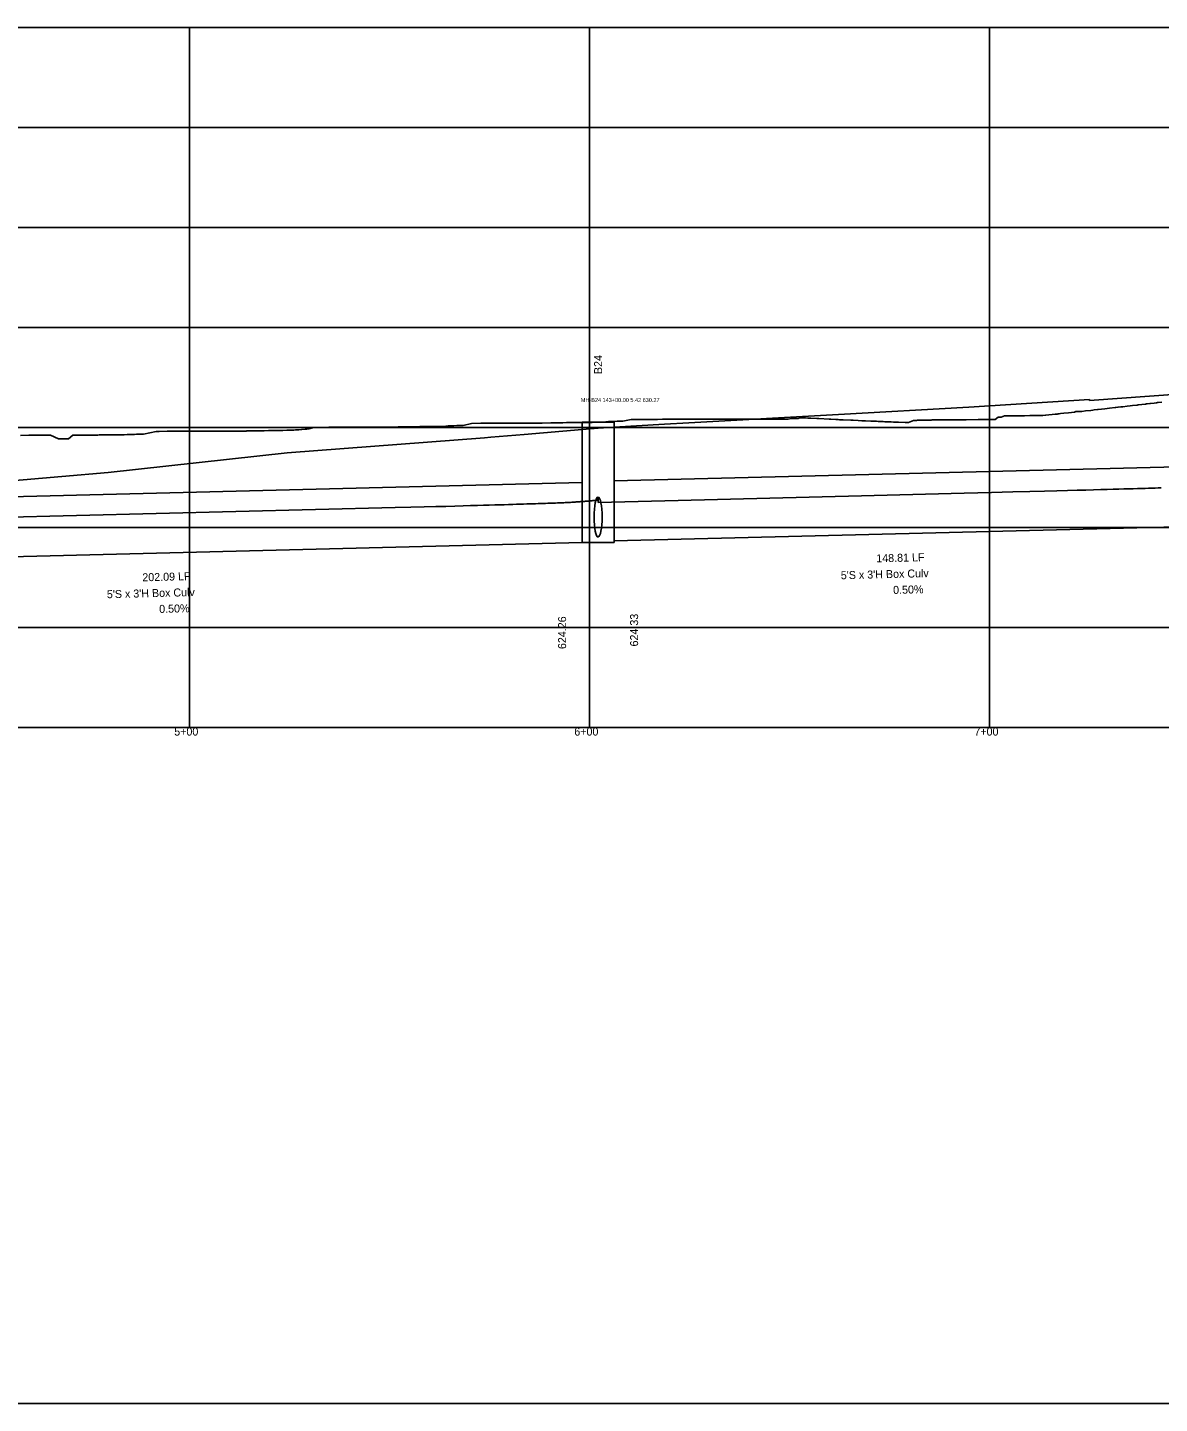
# Model space of a CAD drawing. Extents: x 2253035 to 2279930, y 13774972 to 13793443.
# Drawn here: x 2260421 to 2260703.9, y 13791972.5 to 13792316.4 of the extents above; entities that cross this region are included whole.
import ezdxf

# ---------------------------------------------------------------- set-up
doc = ezdxf.new("R2010")
doc.units = 0
for name, color, linetype in [('Default', 7, 'Continuous'), ('E_Utility_ATT_HH', 7, 'Continuous'), ('E_Utility_ATT_PR_PVC', 7, 'Continuous'), ('E_Utility_Telephone_Telephone Pedestal_TPED_Description', 7, 'Continuous'), ('E_Utillity_Water_Water Line_12in', 7, 'Continuous'), ('E_Utillity_Water_Water Line_1in', 7, 'Continuous'), ('E_Utillity_Water_Water Line_4in', 7, 'Continuous'), ('E_Utillity_Water_Water Line_8in', 7, 'Continuous')]:
    doc.layers.add(name, color=color, linetype=linetype)

msp = doc.modelspace()

# ---------------------------------------------------------------- linework, layer by layer
at = {"layer": 'Default'}
for p, q in [((2260461.48, 13792141.44), (2260461.48, 13792316.44)), ((2260561.48, 13792141.44), (2260561.48, 13792316.44)), ((2260661.48, 13792141.44), (2260661.48, 13792316.44)), ((2259961.48, 13792291.44), (2261350.66, 13792291.44)), ((2259961.48, 13792266.44), (2261350.66, 13792266.44)), ((2259961.48, 13792241.44), (2261350.66, 13792241.44)), ((2259961.48, 13792216.44), (2261350.66, 13792216.44)), ((2259961.48, 13792191.44), (2261350.66, 13792191.44)), ((2259961.48, 13792166.44), (2261350.66, 13792166.44)), ((2258357.4, 13791972.48), (2265626.63, 13791972.48))]:
    msp.add_line(p, q, dxfattribs=at)
msp.add_lwpolyline([(2259961.48, 13792141.44), (2259961.48, 13792316.44), (2261350.66, 13792316.44), (2261350.66, 13792141.44)], close=True, dxfattribs=at)
at = {"layer": 'E_Utility_ATT_PR_PVC'}
msp.add_line((2260563.63, 13792198.87), (2260563.63, 13792197.73), dxfattribs=at)
for points in [[(2260353.54, 13792192.44), (2260512.87, 13792196.42), (2260516.81, 13792196.52), (2260520.15, 13792196.61), (2260523.05, 13792196.69), (2260525.59, 13792196.75), (2260527.86, 13792196.82), (2260529.91, 13792196.87), (2260531.76, 13792196.92), (2260533.45, 13792196.97), (2260535.01, 13792197.02), (2260536.44, 13792197.06), (2260537.78, 13792197.09), (2260539.02, 13792197.13), (2260540.17, 13792197.16), (2260541.26, 13792197.2), (2260542.28, 13792197.23), (2260543.24, 13792197.26), (2260544.14, 13792197.28), (2260545, 13792197.31), (2260545.81, 13792197.34), (2260546.58, 13792197.36), (2260547.31, 13792197.38), (2260548.01, 13792197.41), (2260548.67, 13792197.43), (2260549.3, 13792197.45), (2260549.9, 13792197.47), (2260550.48, 13792197.49), (2260551.03, 13792197.51), (2260551.55, 13792197.52), (2260552.06, 13792197.54), (2260552.54, 13792197.56), (2260553, 13792197.57), (2260553.45, 13792197.59), (2260553.88, 13792197.61), (2260554.29, 13792197.62), (2260554.68, 13792197.64), (2260555.06, 13792197.65), (2260555.42, 13792197.67), (2260555.77, 13792197.68), (2260556.11, 13792197.7), (2260556.44, 13792197.73), (2260556.75, 13792197.75), (2260557.05, 13792197.77), (2260557.34, 13792197.79), (2260557.62, 13792197.81), (2260557.89, 13792197.82), (2260558.15, 13792197.84), (2260558.4, 13792197.86), (2260558.64, 13792197.88), (2260558.87, 13792197.89), (2260559.09, 13792197.91), (2260559.31, 13792197.92), (2260559.52, 13792197.94), (2260559.72, 13792197.96), (2260559.91, 13792197.97), (2260560.09, 13792197.98), (2260560.27, 13792198), (2260560.45, 13792198.01), (2260560.61, 13792198.02), (2260560.77, 13792198.04), (2260560.93, 13792198.05), (2260561.07, 13792198.06), (2260561.22, 13792198.08), (2260561.35, 13792198.09), (2260561.48, 13792198.1), (2260561.61, 13792198.11), (2260561.73, 13792198.12), (2260561.85, 13792198.13), (2260561.96, 13792198.14), (2260562.07, 13792198.15), (2260562.17, 13792198.16), (2260562.27, 13792198.17), (2260562.36, 13792198.18), (2260562.45, 13792198.19), (2260562.54, 13792198.2), (2260562.62, 13792198.21), (2260562.7, 13792198.22), (2260562.77, 13792198.23), (2260562.84, 13792198.24), (2260562.91, 13792198.24), (2260562.97, 13792198.25), (2260563.03, 13792198.26), (2260563.09, 13792198.27), (2260563.14, 13792198.28), (2260563.19, 13792198.28), (2260563.24, 13792198.29), (2260563.28, 13792198.3), (2260563.33, 13792198.31), (2260563.36, 13792198.31), (2260563.4, 13792198.32), (2260563.43, 13792198.33), (2260563.46, 13792198.33), (2260563.49, 13792198.34), (2260563.51, 13792198.34), (2260563.54, 13792198.35), (2260563.55, 13792198.36), (2260563.57, 13792198.36), (2260563.59, 13792198.37), (2260563.6, 13792198.37), (2260563.61, 13792198.38), (2260563.62, 13792198.39), (2260563.62, 13792198.39), (2260563.62, 13792198.4), (2260563.63, 13792198.4), (2260563.63, 13792198.87)], [(2260563.63, 13792197.73), (2260583.67, 13792198.23), (2260629.46, 13792199.38), (2260645.48, 13792199.78), (2260655.12, 13792200.03), (2260661.98, 13792200.2), (2260667.27, 13792200.34), (2260671.57, 13792200.45), (2260675.18, 13792200.55), (2260678.28, 13792200.63), (2260680.99, 13792200.7), (2260683.39, 13792200.77), (2260685.54, 13792200.83), (2260687.49, 13792200.88), (2260689.26, 13792200.93), (2260690.88, 13792200.98), (2260692.38, 13792201.02), (2260693.76, 13792201.06), (2260695.05, 13792201.1), (2260696.25, 13792201.13), (2260697.38, 13792201.16), (2260698.43, 13792201.2), (2260699.42, 13792201.23), (2260700.36, 13792201.25), (2260701.24, 13792201.28), (2260702.08, 13792201.31), (2260702.87, 13792201.33), (2260703.62, 13792201.36), (2260704.34, 13792201.38)]]:
    msp.add_lwpolyline(points, dxfattribs=at)
at = {"layer": 'E_Utillity_Water_Water Line_12in'}
msp.add_lwpolyline([(2260559.63, 13792217.78), (2260567.63, 13792217.78), (2260567.63, 13792187.74), (2260559.63, 13792187.74)], close=True, dxfattribs=at)
at = {"layer": 'E_Utillity_Water_Water Line_1in'}
msp.add_lwpolyline([(2260385.04, 13792200.38), (2260429.58, 13792204.18), (2260441.19, 13792205.21), (2260485.92, 13792210.11), (2260535.24, 13792213.87), (2260536.85, 13792214.02), (2260545.19, 13792214.71), (2260559.63, 13792215.93), (2260559.63, 13792215.93), (2260563.63, 13792216.25), (2260563.63, 13792216.25), (2260567.63, 13792216.57), (2260567.63, 13792216.57), (2260580.25, 13792217.3), (2260586.29, 13792217.65), (2260623.69, 13792219.68), (2260656.31, 13792221.55), (2260686.45, 13792223.42), (2260686.48, 13792223.21), (2260716.44, 13792225.36)], dxfattribs=at)
at = {"layer": 'E_Utillity_Water_Water Line_4in'}
for p, q in [((2260567.63, 13792203.1), (2260716.44, 13792206.82)), ((2260357.54, 13792197.69), (2260559.63, 13792202.74)), ((2260567.63, 13792188.1), (2260716.44, 13792191.82)), ((2260357.54, 13792182.69), (2260559.63, 13792187.74))]:
    msp.add_line(p, q, dxfattribs=at)
msp.add_ellipse((2260563.63, 13792194.07), major_axis=(0, 5), ratio=0.2, dxfattribs=at)
at = {"layer": 'E_Utillity_Water_Water Line_8in'}
msp.add_lwpolyline([(2260419.22, 13792214.49), (2260421.3, 13792214.5), (2260421.35, 13792214.5), (2260423.52, 13792214.5), (2260424.01, 13792214.5), (2260424.56, 13792214.5), (2260426.79, 13792214.51), (2260428.78, 13792213.65), (2260431.26, 13792213.66), (2260432.38, 13792214.52), (2260432.64, 13792214.53), (2260433.62, 13792214.53), (2260433.99, 13792214.55), (2260435.27, 13792214.55), (2260437.23, 13792214.55), (2260437.41, 13792214.56), (2260438.62, 13792214.57), (2260438.92, 13792214.59), (2260439.85, 13792214.59), (2260441.77, 13792214.59), (2260442.26, 13792214.63), (2260443.62, 13792214.63), (2260445.14, 13792214.64), (2260445.93, 13792214.72), (2260447.74, 13792214.73), (2260448.23, 13792214.79), (2260448.35, 13792214.79), (2260448.62, 13792214.79), (2260450.04, 13792214.8), (2260453.16, 13792215.44), (2260453.41, 13792215.45), (2260453.95, 13792215.46), (2260455.93, 13792215.51), (2260459.29, 13792215.52), (2260459.5, 13792215.52), (2260461.49, 13792215.52), (2260461.53, 13792215.52), (2260461.58, 13792215.52), (2260463.7, 13792215.53), (2260464.17, 13792215.53), (2260466.07, 13792215.53), (2260468.03, 13792215.53), (2260468.76, 13792215.53), (2260470.2, 13792215.54), (2260472.3, 13792215.54), (2260472.65, 13792215.56), (2260473.62, 13792215.56), (2260473.65, 13792215.56), (2260473.86, 13792215.57), (2260475.14, 13792215.57), (2260475.56, 13792215.57), (2260475.67, 13792215.58), (2260475.86, 13792215.59), (2260477.73, 13792215.59), (2260478.47, 13792215.59), (2260478.97, 13792215.59), (2260480.14, 13792215.6), (2260481.25, 13792215.67), (2260482.02, 13792215.68), (2260483.57, 13792215.68), (2260483.62, 13792215.68), (2260483.97, 13792215.71), (2260484.55, 13792215.72), (2260484.83, 13792215.74), (2260485.8, 13792215.75), (2260486.57, 13792215.83), (2260487.61, 13792215.83), (2260487.98, 13792215.88), (2260488.62, 13792215.88), (2260488.86, 13792215.91), (2260489.51, 13792215.92), (2260490.46, 13792216.08), (2260490.8, 13792216.08), (2260491.34, 13792216.09), (2260492.57, 13792216.44), (2260494.12, 13792216.48), (2260494.39, 13792216.49), (2260496.31, 13792216.54), (2260499.58, 13792216.54), (2260499.79, 13792216.54), (2260502.46, 13792216.55), (2260502.51, 13792216.55), (2260503.87, 13792216.55), (2260504.33, 13792216.55), (2260504.85, 13792216.55), (2260507.33, 13792216.56), (2260508.8, 13792216.56), (2260510.2, 13792216.56), (2260512.25, 13792216.56), (2260512.68, 13792216.58), (2260513.62, 13792216.59), (2260514.23, 13792216.61), (2260515.41, 13792216.62), (2260517.23, 13792216.62), (2260517.51, 13792216.64), (2260518.62, 13792216.64), (2260519.1, 13792216.67), (2260519.94, 13792216.67), (2260521.67, 13792216.67), (2260522.43, 13792216.73), (2260523.62, 13792216.74), (2260524.95, 13792216.74), (2260526.15, 13792216.86), (2260527.61, 13792216.87), (2260528.33, 13792216.96), (2260528.42, 13792216.96), (2260528.62, 13792216.96), (2260528.8, 13792216.97), (2260529.92, 13792216.97), (2260531.97, 13792217.44), (2260534.31, 13792217.5), (2260534.82, 13792217.52), (2260536.69, 13792217.56), (2260539.88, 13792217.57), (2260540.07, 13792217.57), (2260541.96, 13792217.57), (2260541.99, 13792217.57), (2260542.04, 13792217.57), (2260544.04, 13792217.58), (2260544.49, 13792217.58), (2260546.29, 13792217.58), (2260548.15, 13792217.58), (2260548.84, 13792217.58), (2260549.62, 13792217.58), (2260551.81, 13792217.59), (2260552.34, 13792217.61), (2260552.46, 13792217.61), (2260553.62, 13792217.61), (2260553.78, 13792217.62), (2260554.79, 13792217.62), (2260555.7, 13792217.67), (2260557.8, 13792217.67), (2260558.62, 13792217.67), (2260559.19, 13792217.71), (2260559.63, 13792217.71), (2260559.63, 13792217.71), (2260560.34, 13792217.71), (2260562.16, 13792217.71), (2260563, 13792217.78), (2260563.13, 13792217.78), (2260563.62, 13792217.78), (2260563.63, 13792217.78), (2260563.63, 13792217.78), (2260564.87, 13792217.78), (2260566.24, 13792217.92), (2260567.55, 13792217.92), (2260567.63, 13792217.93), (2260567.63, 13792217.93), (2260568.37, 13792218.02), (2260568.44, 13792218.02), (2260568.62, 13792218.02), (2260568.78, 13792218.02), (2260569.81, 13792218.01), (2260571.91, 13792218.44), (2260573.23, 13792218.44), (2260573.39, 13792218.44), (2260573.71, 13792218.44), (2260574.94, 13792218.44), (2260576.18, 13792218.44), (2260578.51, 13792218.44), (2260579.74, 13792218.54), (2260581.62, 13792218.54), (2260581.67, 13792218.54), (2260581.67, 13792218.54), (2260583.74, 13792218.53), (2260584.19, 13792218.53), (2260584.71, 13792218.53), (2260587.22, 13792218.52), (2260588.75, 13792218.52), (2260589.58, 13792218.52), (2260591.95, 13792218.51), (2260592.21, 13792218.52), (2260592.34, 13792218.52), (2260593.63, 13792218.52), (2260593.69, 13792218.52), (2260594.87, 13792218.52), (2260597.06, 13792218.51), (2260597.36, 13792218.53), (2260598.63, 13792218.52), (2260598.82, 13792218.53), (2260600.24, 13792218.53), (2260602.54, 13792218.52), (2260602.78, 13792218.54), (2260602.95, 13792218.54), (2260603.63, 13792218.53), (2260603.83, 13792218.55), (2260604.56, 13792218.54), (2260606.56, 13792218.53), (2260606.91, 13792218.57), (2260608.63, 13792218.55), (2260608.96, 13792218.55), (2260611.12, 13792218.53), (2260611.91, 13792218.71), (2260613.51, 13792218.67), (2260613.57, 13792218.67), (2260613.63, 13792218.7), (2260614.03, 13792218.91), (2260614.28, 13792218.9), (2260614.73, 13792218.88), (2260615.43, 13792218.84), (2260616.05, 13792218.81), (2260616.8, 13792218.77), (2260618.29, 13792218.69), (2260618.57, 13792218.68), (2260618.63, 13792218.68), (2260618.71, 13792218.67), (2260618.83, 13792218.67), (2260621.37, 13792218.54), (2260621.65, 13792218.53), (2260621.79, 13792218.52), (2260623.04, 13792218.46), (2260623.38, 13792218.44), (2260623.62, 13792218.43), (2260623.63, 13792218.43), (2260624, 13792218.41), (2260624.05, 13792218.41), (2260624.91, 13792218.37), (2260626.8, 13792218.28), (2260627.05, 13792218.27), (2260627.09, 13792218.27), (2260627.36, 13792218.26), (2260628.63, 13792218.2), (2260629.57, 13792218.16), (2260629.93, 13792218.14), (2260629.94, 13792218.14), (2260630.49, 13792218.12), (2260631.8, 13792218.06), (2260632.63, 13792218.02), (2260633.24, 13792218), (2260633.63, 13792217.98), (2260634.08, 13792217.96), (2260634.88, 13792217.93), (2260635.27, 13792217.91), (2260636.9, 13792217.85), (2260637.49, 13792217.82), (2260638.02, 13792217.8), (2260638.45, 13792217.78), (2260638.64, 13792217.77), (2260638.75, 13792217.77), (2260640.34, 13792217.71), (2260640.82, 13792217.69), (2260641.22, 13792217.67), (2260642.49, 13792218.21), (2260642.51, 13792218.21), (2260642.53, 13792218.22), (2260642.54, 13792218.22), (2260643.23, 13792218.21), (2260643.46, 13792218.29), (2260643.64, 13792218.29), (2260643.65, 13792218.29), (2260644.31, 13792218.29), (2260644.95, 13792218.28), (2260645.21, 13792218.33), (2260645.34, 13792218.33), (2260645.34, 13792218.33), (2260645.34, 13792218.33), (2260645.67, 13792218.33), (2260645.67, 13792218.33), (2260645.67, 13792218.33), (2260646.87, 13792218.32), (2260647.16, 13792218.37), (2260647.42, 13792218.37), (2260648.6, 13792218.36), (2260648.64, 13792218.37), (2260649.75, 13792218.37), (2260649.8, 13792218.37), (2260652.15, 13792218.37), (2260652.39, 13792218.39), (2260652.59, 13792218.38), (2260652.77, 13792218.38), (2260652.89, 13792218.39), (2260653.01, 13792218.39), (2260653.04, 13792218.39), (2260653.07, 13792218.39), (2260653.31, 13792218.39), (2260653.56, 13792218.39), (2260655.4, 13792218.4), (2260655.62, 13792218.41), (2260658.62, 13792218.42), (2260659.1, 13792218.42), (2260661.09, 13792218.43), (2260661.11, 13792218.43), (2260661.3, 13792218.43), (2260661.32, 13792218.43), (2260662.72, 13792218.44), (2260662.85, 13792218.44), (2260663.62, 13792219.01), (2260663.7, 13792219.01), (2260663.72, 13792219.03), (2260664.4, 13792219.05), (2260665.17, 13792219.36), (2260666.29, 13792219.37), (2260667.82, 13792219.38), (2260668.61, 13792219.39), (2260668.64, 13792219.39), (2260670.21, 13792219.41), (2260671.57, 13792219.42), (2260671.67, 13792219.43), (2260673.64, 13792219.44), (2260674.75, 13792219.44), (2260675.43, 13792219.51), (2260675.54, 13792219.53), (2260677.85, 13792219.77), (2260678.33, 13792219.82), (2260678.64, 13792219.85), (2260678.89, 13792219.88), (2260679.23, 13792219.92), (2260680.05, 13792220.01), (2260681.22, 13792220.13), (2260682.72, 13792220.3), (2260683, 13792220.42), (2260683.48, 13792220.43), (2260683.64, 13792220.44), (2260683.65, 13792220.44), (2260684.07, 13792220.44), (2260684.48, 13792220.49), (2260684.53, 13792220.49), (2260685.48, 13792220.6), (2260686.76, 13792220.74), (2260687.32, 13792220.8), (2260687.61, 13792220.84), (2260688.45, 13792220.93), (2260688.65, 13792220.95), (2260689.49, 13792221.05), (2260690.3, 13792221.14), (2260691.42, 13792221.26), (2260692.88, 13792221.43), (2260692.92, 13792221.43), (2260693, 13792221.44), (2260693.55, 13792221.51), (2260693.65, 13792221.52), (2260694.25, 13792221.59), (2260694.37, 13792221.6), (2260694.38, 13792221.6), (2260694.79, 13792221.65), (2260695.83, 13792221.77), (2260696.63, 13792221.86), (2260697.17, 13792221.93), (2260698.34, 13792222.06), (2260698.65, 13792222.1), (2260698.65, 13792222.1), (2260698.65, 13792222.1), (2260700.49, 13792222.32), (2260700.72, 13792222.34), (2260700.88, 13792222.36), (2260701.57, 13792222.44), (2260701.64, 13792222.45), (2260701.66, 13792222.45), (2260702.59, 13792222.57), (2260703.18, 13792222.63), (2260703.47, 13792222.67), (2260703.65, 13792222.69), (2260704.53, 13792222.8)], dxfattribs=at)

# ---------------------------------------------------------------- texts
at = {"layer": 'Default'}
for s, p in [('5+00', (2260457.68, 13792139.44)), ('6+00', (2260557.68, 13792139.44)), ('7+00', (2260657.68, 13792139.44))]:
    msp.add_text(s, height=2, dxfattribs=at).set_placement(p)
at = {"layer": 'E_Utility_ATT_HH'}
for s, rotation, p in [('B24', 90, (2260564.63, 13792229.81)), ('148.81 LF', 1.4321, (2260633.18, 13792182.74)), ('202.09 LF', 1.4321, (2260449.73, 13792178)), ("5'S x 3'H Box Culv", 1.4321, (2260624.32, 13792178.51)), ("5'S x 3'H Box Culv", 1.4321, (2260440.87, 13792173.77)), ('0.50%', 1.4321, (2260637.39, 13792174.84)), ('0.50%', 1.4321, (2260453.94, 13792170.1)), ('624.26', 90, (2260555.63, 13792161.07)), ('624.33', 90, (2260573.63, 13792161.72))]:
    msp.add_text(s, height=2, rotation=rotation, dxfattribs=at).set_placement(p)
at = {"layer": 'E_Utility_Telephone_Telephone Pedestal_TPED_Description'}
msp.add_text('MH-B24 143+00.00 5.42 630.27', height=1, rotation=0, dxfattribs=at).set_placement((2260559.3, 13792222.83))

doc.saveas('drawing.dxf')
